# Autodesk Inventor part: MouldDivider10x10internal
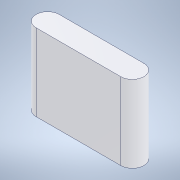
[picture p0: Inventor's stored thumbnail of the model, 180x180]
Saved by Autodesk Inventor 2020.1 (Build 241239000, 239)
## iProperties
Created: 2021-11
Part Number: MouldDivider10x10internal
Material: Generic
Document SubType Name: Modeling
Designer: c14576jb
Density: 1 g/cm^3
Appearance: Default
Author: c14576jb
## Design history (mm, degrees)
sketch "Sketch1"
  geometry: L1 (0, 0)-(14, 0); L2 (14, 0)-(14, -3); L3 (14, -3)-(0, -3); L4 (0, -3)-(0, 0)
  constraints: 8 end point, 2 parallel, 1 horizontal, 1 perpendicular
  dimensions: "d0" = 14 distance of L2.end L3.end; "d1" = 3 distance of L1.end L2.end
extrude "Extrusion1" new body sketch "Sketch1" distance "d2" = 10; taper "d3" = 0 deg
fillet "Fillet1"
fillet "Fillet2"
body "Solid1"
